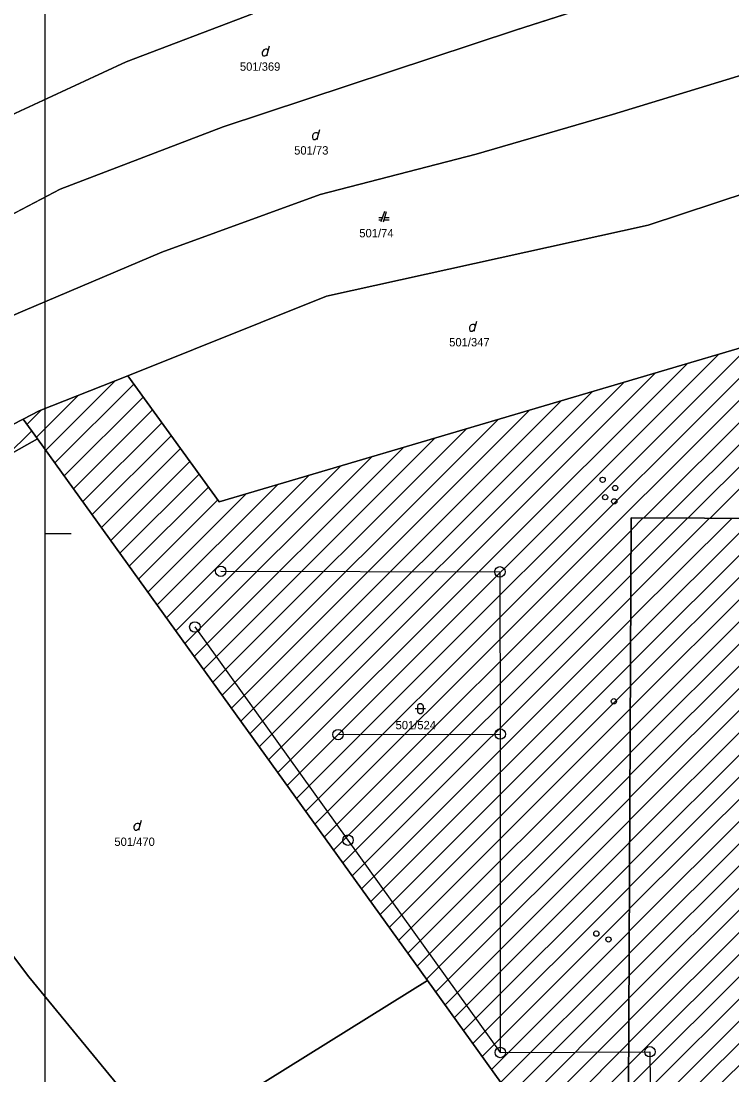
# Model space of a CAD drawing. Extents: x -264309 to -263505, y -1242443 to -1241763.
# Drawn here: x -264215.4 to -264079.6, y -1242302.6 to -1242101 of the extents above; entities that cross this region are included whole.
import ezdxf

# ---------------------------------------------------------------- set-up
doc = ezdxf.new("R2010")
doc.units = 0
for name, color, linetype in [('KFA_DAZDOVA_KANALIZACIA_vetva_F', 7, 'Continuous'), ('KFA_SO_40-3_SACHTY_POKLOPY', 7, 'Continuous'), ('KN_2019_08_16_KLADPAR', 7, 'Continuous'), ('RAM_NA_TLAC_10xA4_1-500', 7, 'Continuous'), ('SRAFY_PARCELY', 7, 'Continuous')]:
    doc.layers.add(name, color=color, linetype=linetype)

msp = doc.modelspace()

# ---------------------------------------------------------------- linework, layer by layer
at = {"layer": 'KFA_DAZDOVA_KANALIZACIA_vetva_F'}
msp.add_line((-264154.85, -1242237.52), (-264123.86, -1242237.42), dxfattribs=at)
for points in [[(-264177.27, -1242206.27), (-264123.92, -1242206.39), (-264123.86, -1242237.42), (-264123.84, -1242298.32)], [(-264182.21, -1242216.93), (-264152.95, -1242257.71), (-264123.84, -1242298.32)], [(-264123.84, -1242298.32), (-264095.25, -1242298.17), (-264095.21, -1242304.15)]]:
    msp.add_lwpolyline(points, dxfattribs=at)
for centre in [(-264177.27, -1242206.27), (-264123.92, -1242206.39), (-264182.21, -1242216.93), (-264154.85, -1242237.52), (-264123.86, -1242237.42), (-264152.95, -1242257.71), (-264123.84, -1242298.32), (-264095.25, -1242298.17)]:
    msp.add_circle(centre, 1, dxfattribs=at)
at = {"layer": 'KFA_SO_40-3_SACHTY_POKLOPY'}
for centre in [(-264104.28, -1242188.78), (-264101.88, -1242190.34), (-264103.81, -1242192.11), (-264102.06, -1242192.9), (-264102.14, -1242231.14), (-264105.49, -1242275.58), (-264103.16, -1242276.7)]:
    msp.add_circle(centre, 0.5, dxfattribs=at)
at = {"layer": 'KN_2019_08_16_KLADPAR'}
for p, q in [((-264081.08, -1242089.93), (-264120.91, -1242102.78)), ((-264195.32, -1242108.83), (-264171.23, -1242099.67)), ((-264120.91, -1242102.78), (-264176.83, -1242121.28)), ((-264168.2, -1242106.7), (-264167.93, -1242105.8)), ((-264231.66, -1242125.67), (-264195.32, -1242108.83)), ((-264176.83, -1242121.28), (-264207.96, -1242133.21)), ((-264158.59, -1242122.67), (-264158.32, -1242121.77)), ((-264207.96, -1242133.21), (-264246.81, -1242153.57)), ((-264146.39, -1242138.64), (-264147.07, -1242138.64)), ((-264145.97, -1242137.44), (-264146.67, -1242139.44)), ((-264146.17, -1242139.44), (-264145.57, -1242137.44)), ((-264145.07, -1242138.64), (-264145.93, -1242138.64)), ((-264147.07, -1242139.04), (-264146.53, -1242139.04)), ((-264146.05, -1242139.04), (-264145.07, -1242139.04)), ((-264128.59, -1242159.34), (-264128.32, -1242158.44)), ((-264192.7, -1242254.78), (-264192.43, -1242253.88))]:
    msp.add_line(p, q, dxfattribs=at)
for points in [[(-264136.47, -1242066.18), (-264126.66, -1242067.07), (-264113.43, -1242067.44), (-264093.07, -1242066.63), (-264091, -1242071.24), (-264106.54, -1242077.18), (-264118.83, -1242081.48), (-264143.3, -1242090.1), (-264171.23, -1242099.67), (-264195.32, -1242108.83), (-264231.66, -1242125.67), (-264256.42, -1242138.67), (-264258.61, -1242135.22), (-264265.78, -1242123.95), (-264240.95, -1242110.43), (-264231.21, -1242105.15), (-264197.75, -1242090.71), (-264182.59, -1242084.17), (-264140.89, -1242068)], [(-264246.81, -1242153.57), (-264207.96, -1242133.21), (-264176.83, -1242121.28), (-264120.91, -1242102.78), (-264081.08, -1242089.93), (-264076.9, -1242098.2), (-264076.93, -1242111.1), (-264102.41, -1242118.92), (-264128.45, -1242126.51), (-264158.28, -1242134.19), (-264188.56, -1242145.27), (-264215.11, -1242156.51), (-264222.8, -1242159.81), (-264237.43, -1242168.42)], [(-264076.93, -1242111.1), (-264076.98, -1242129.46), (-264076.3, -1242133.7), (-264095.55, -1242140.08), (-264157.05, -1242153.68), (-264195.05, -1242168.92), (-264211.96, -1242175.6), (-264215.03, -1242177.17), (-264227.71, -1242183.68), (-264237.43, -1242168.42), (-264222.8, -1242159.81), (-264215.11, -1242156.51), (-264188.56, -1242145.27), (-264158.28, -1242134.19), (-264128.45, -1242126.51), (-264102.41, -1242118.92)], [(-264195.05, -1242168.92), (-264157.05, -1242153.68), (-264095.55, -1242140.08), (-264076.3, -1242133.7), (-264074.04, -1242162.41), (-264177.6, -1242192.97)], [(-264212.29, -1242180.92), (-264215.03, -1242177.17), (-264211.96, -1242175.6), (-264195.05, -1242168.92), (-264177.6, -1242192.97), (-264074.04, -1242162.41), (-264070.8, -1242196.19), (-264098.84, -1242196.05), (-264099.36, -1242306.05), (-264115.27, -1242315.84), (-264137.78, -1242284.52)], [(-264264.01, -1242217.15), (-264233.51, -1242192.88), (-264212.29, -1242180.92), (-264137.78, -1242284.52), (-264187.74, -1242315.7), (-264213.92, -1242283.84)], [(-263950.84, -1242196.76), (-263951.29, -1242290.6), (-263951.37, -1242306.76), (-264045.86, -1242306.31), (-264099.36, -1242306.05), (-264098.84, -1242196.05), (-264070.8, -1242196.19)], [(-264187.74, -1242315.7), (-264201.06, -1242324.01), (-264208.73, -1242314.82), (-264233.72, -1242281.89), (-264276.4, -1242228.3), (-264264.01, -1242217.15), (-264213.92, -1242283.84)], [(-264139.61, -1242232.05), (-264139.51, -1242231.76), (-264139.26, -1242231.58), (-264138.95, -1242231.58), (-264138.7, -1242231.76), (-264138.6, -1242232.05), (-264138.6, -1242233.05), (-264138.7, -1242233.34), (-264138.95, -1242233.52), (-264139.26, -1242233.52), (-264139.51, -1242233.34), (-264139.61, -1242233.05)], [(-264187.74, -1242315.7), (-264137.78, -1242284.52), (-264115.27, -1242315.84), (-264103.64, -1242332.03), (-264146.94, -1242365.35)]]:
    msp.add_lwpolyline(points, close=True, dxfattribs=at)
for points in [[(-264168.38, -1242107.69), (-264168.38, -1242107.42), (-264168.2, -1242106.7), (-264168.29, -1242106.52), (-264168.47, -1242106.43), (-264168.74, -1242106.43), (-264169.01, -1242106.52), (-264169.19, -1242106.7), (-264169.37, -1242106.97), (-264169.37, -1242107.33), (-264169.28, -1242107.6), (-264169.1, -1242107.69), (-264168.83, -1242107.69), (-264168.65, -1242107.6), (-264168.38, -1242107.42)], [(-264158.77, -1242123.66), (-264158.77, -1242123.39), (-264158.59, -1242122.67), (-264158.68, -1242122.49), (-264158.86, -1242122.4), (-264159.13, -1242122.4), (-264159.4, -1242122.49), (-264159.58, -1242122.67), (-264159.76, -1242122.94), (-264159.76, -1242123.3), (-264159.67, -1242123.57), (-264159.49, -1242123.66), (-264159.22, -1242123.66), (-264159.04, -1242123.57), (-264158.77, -1242123.39)], [(-264128.77, -1242160.33), (-264128.77, -1242160.06), (-264128.59, -1242159.34), (-264128.68, -1242159.16), (-264128.86, -1242159.07), (-264129.13, -1242159.07), (-264129.4, -1242159.16), (-264129.58, -1242159.34), (-264129.76, -1242159.61), (-264129.76, -1242159.97), (-264129.67, -1242160.24), (-264129.49, -1242160.33), (-264129.22, -1242160.33), (-264129.04, -1242160.24), (-264128.77, -1242160.06)], [(-264240.46, -1242310.08), (-264272.98, -1242263.62), (-264276.57, -1242250.38), (-264276.98, -1242219.72), (-264277.77, -1242218.42), (-264255.3, -1242202.84), (-264227.71, -1242183.68), (-264215.03, -1242177.17), (-264212.29, -1242180.92), (-264233.51, -1242192.88), (-264264.01, -1242217.15), (-264276.4, -1242228.3), (-264233.72, -1242281.89), (-264208.73, -1242314.82)], [(-264140.11, -1242232.55), (-264138.84, -1242232.55), (-264138.11, -1242232.55)], [(-264192.88, -1242255.77), (-264192.88, -1242255.5), (-264192.7, -1242254.78), (-264192.79, -1242254.6), (-264192.97, -1242254.51), (-264193.24, -1242254.51), (-264193.51, -1242254.6), (-264193.69, -1242254.78), (-264193.87, -1242255.05), (-264193.87, -1242255.41), (-264193.78, -1242255.68), (-264193.6, -1242255.77), (-264193.33, -1242255.77), (-264193.15, -1242255.68), (-264192.88, -1242255.5)]]:
    msp.add_lwpolyline(points, dxfattribs=at)
at = {"layer": 'RAM_NA_TLAC_10xA4_1-500'}
msp.add_line((-264210.83, -1242199.04), (-264205.83, -1242199.04), dxfattribs=at)
msp.add_lwpolyline([(-264210.83, -1242050.54), (-264105.83, -1242050.54), (-264000.83, -1242050.54), (-263895.83, -1242050.54), (-263790.83, -1242050.54), (-263685.83, -1242050.54), (-263685.83, -1242199.04), (-263685.83, -1242347.54), (-263790.83, -1242347.54), (-263895.83, -1242347.54), (-264000.83, -1242347.54), (-264105.83, -1242347.54), (-264210.83, -1242347.54), (-264210.83, -1242199.04)], close=True, dxfattribs=at)
at = {"layer": 'SRAFY_PARCELY'}
for p, q in [((-264164.58, -1242247.25), (-264082.12, -1242164.8)), ((-264162.81, -1242249.72), (-264076.1, -1242163.02)), ((-264166.36, -1242244.79), (-264088.14, -1242166.57)), ((-264161.03, -1242252.19), (-264073.8, -1242164.95)), ((-264168.13, -1242242.32), (-264094.16, -1242168.35)), ((-264159.26, -1242254.66), (-264073.42, -1242168.82)), ((-264210.73, -1242183.09), (-264197.54, -1242169.9)), ((-264208.95, -1242185.56), (-264193.9, -1242170.51)), ((-264169.91, -1242239.85), (-264100.18, -1242170.12)), ((-264212.5, -1242180.63), (-264204.55, -1242172.67)), ((-264171.68, -1242237.38), (-264106.2, -1242171.9)), ((-264096.42, -1242196.06), (-264073.05, -1242172.7)), ((-264207.18, -1242188.03), (-264192.12, -1242172.96)), ((-264173.46, -1242234.92), (-264112.22, -1242173.68)), ((-264214.3, -1242178.17), (-264211.57, -1242175.44)), ((-264205.4, -1242190.5), (-264190.33, -1242175.42)), ((-264175.23, -1242232.45), (-264118.24, -1242175.45)), ((-264092.2, -1242196.08), (-264072.68, -1242176.57)), ((-264203.63, -1242192.96), (-264188.55, -1242177.88)), ((-264177.01, -1242229.98), (-264124.25, -1242177.23)), ((-264218.33, -1242184.32), (-264213.4, -1242179.4)), ((-264201.85, -1242195.43), (-264186.76, -1242180.34)), ((-264180.56, -1242225.04), (-264136.29, -1242180.78)), ((-264178.78, -1242227.51), (-264130.27, -1242179)), ((-264087.98, -1242196.1), (-264072.31, -1242180.44)), ((-264200.08, -1242197.9), (-264184.98, -1242182.8)), ((-264182.33, -1242222.58), (-264142.31, -1242182.56)), ((-264184.11, -1242220.11), (-264148.33, -1242184.33)), ((-264083.75, -1242196.13), (-264071.94, -1242184.31)), ((-264198.3, -1242200.37), (-264183.2, -1242185.26)), ((-264185.88, -1242217.64), (-264154.35, -1242186.11)), ((-264196.53, -1242202.83), (-264181.41, -1242187.72)), ((-264187.66, -1242215.17), (-264160.37, -1242187.88)), ((-264194.75, -1242205.3), (-264179.63, -1242190.18)), ((-264189.43, -1242212.71), (-264166.39, -1242189.66)), ((-264192.98, -1242207.77), (-264177.84, -1242192.63)), ((-264191.2, -1242210.24), (-264172.4, -1242191.44)), ((-264099.35, -1242304.97), (-263990.95, -1242196.57)), ((-264099.33, -1242300.71), (-263995.17, -1242196.55)), ((-264099.31, -1242296.45), (-263999.39, -1242196.53)), ((-264099.29, -1242292.19), (-264003.62, -1242196.51)), ((-264099.27, -1242287.92), (-264007.84, -1242196.49)), ((-264099.25, -1242283.66), (-264012.06, -1242196.47)), ((-264099.23, -1242279.4), (-264016.29, -1242196.45)), ((-264099.21, -1242275.14), (-264020.51, -1242196.43)), ((-264099.19, -1242270.87), (-264024.73, -1242196.41)), ((-264099.17, -1242266.61), (-264028.95, -1242196.39)), ((-264099.15, -1242262.35), (-264033.18, -1242196.37)), ((-264099.13, -1242258.08), (-264037.4, -1242196.35)), ((-264099.11, -1242253.82), (-264041.62, -1242196.33)), ((-264099.09, -1242249.56), (-264045.84, -1242196.31)), ((-264099.07, -1242245.3), (-264050.07, -1242196.29)), ((-264099.05, -1242241.03), (-264054.29, -1242196.27)), ((-264099.03, -1242236.77), (-264058.51, -1242196.25)), ((-264099.01, -1242232.51), (-264062.73, -1242196.23)), ((-264098.99, -1242228.24), (-264066.96, -1242196.21)), ((-264098.97, -1242223.98), (-264071.18, -1242196.19)), ((-264098.95, -1242219.72), (-264075.4, -1242196.17)), ((-264098.93, -1242215.46), (-264079.62, -1242196.15)), ((-264098.91, -1242211.19), (-264083.84, -1242196.12)), ((-264098.89, -1242206.93), (-264088.06, -1242196.1)), ((-264098.87, -1242202.67), (-264092.29, -1242196.08)), ((-264098.85, -1242198.4), (-264096.51, -1242196.06)), ((-264096.2, -1242306.07), (-263986.73, -1242196.59)), ((-264091.98, -1242306.09), (-263982.5, -1242196.61)), ((-264087.76, -1242306.11), (-263978.28, -1242196.63)), ((-264083.54, -1242306.13), (-263974.06, -1242196.65)), ((-264157.48, -1242257.13), (-264098.85, -1242198.49)), ((-264155.71, -1242259.59), (-264098.87, -1242202.76)), ((-264153.93, -1242262.06), (-264098.89, -1242207.02)), ((-264152.16, -1242264.53), (-264098.91, -1242211.28)), ((-264150.38, -1242267), (-264098.93, -1242215.55)), ((-264148.61, -1242269.46), (-264098.95, -1242219.81)), ((-264146.83, -1242271.93), (-264098.97, -1242224.07)), ((-264145.06, -1242274.4), (-264098.99, -1242228.33)), ((-264143.28, -1242276.87), (-264099.01, -1242232.6)), ((-264141.51, -1242279.34), (-264099.03, -1242236.86)), ((-264139.73, -1242281.8), (-264099.05, -1242241.12)), ((-264137.96, -1242284.27), (-264099.07, -1242245.39)), ((-264136.18, -1242286.74), (-264099.09, -1242249.65)), ((-264134.41, -1242289.21), (-264099.11, -1242253.91)), ((-264132.64, -1242291.68), (-264099.13, -1242258.17)), ((-264130.86, -1242294.14), (-264099.15, -1242262.44)), ((-264129.09, -1242296.61), (-264099.17, -1242266.7)), ((-264127.31, -1242299.08), (-264099.19, -1242270.96)), ((-264125.54, -1242301.55), (-264099.21, -1242275.22)), ((-264123.77, -1242304.02), (-264099.23, -1242279.49)), ((-264121.99, -1242306.49), (-264099.25, -1242283.75)), ((-264120.22, -1242308.96), (-264099.27, -1242288.01)), ((-264118.44, -1242311.42), (-264099.29, -1242292.28)), ((-264116.67, -1242313.89), (-264099.32, -1242296.54)), ((-264112.94, -1242314.41), (-264099.34, -1242300.8))]:
    msp.add_line(p, q, dxfattribs=at)

# ---------------------------------------------------------------- texts
at = {"layer": 'KN_2019_08_16_KLADPAR'}
for s, p in [('501/369', (-264173.61, -1242110.54)), ('501/73', (-264163.24, -1242126.57)), ('501/74', (-264150.79, -1242142.4)), ('501/347', (-264133.61, -1242163.26)), ('501/524', (-264143.86, -1242236.5)), ('501/470', (-264197.6, -1242258.81))]:
    msp.add_text(s, height=1.6, dxfattribs=at).set_placement(p)

doc.saveas('drawing.dxf')
